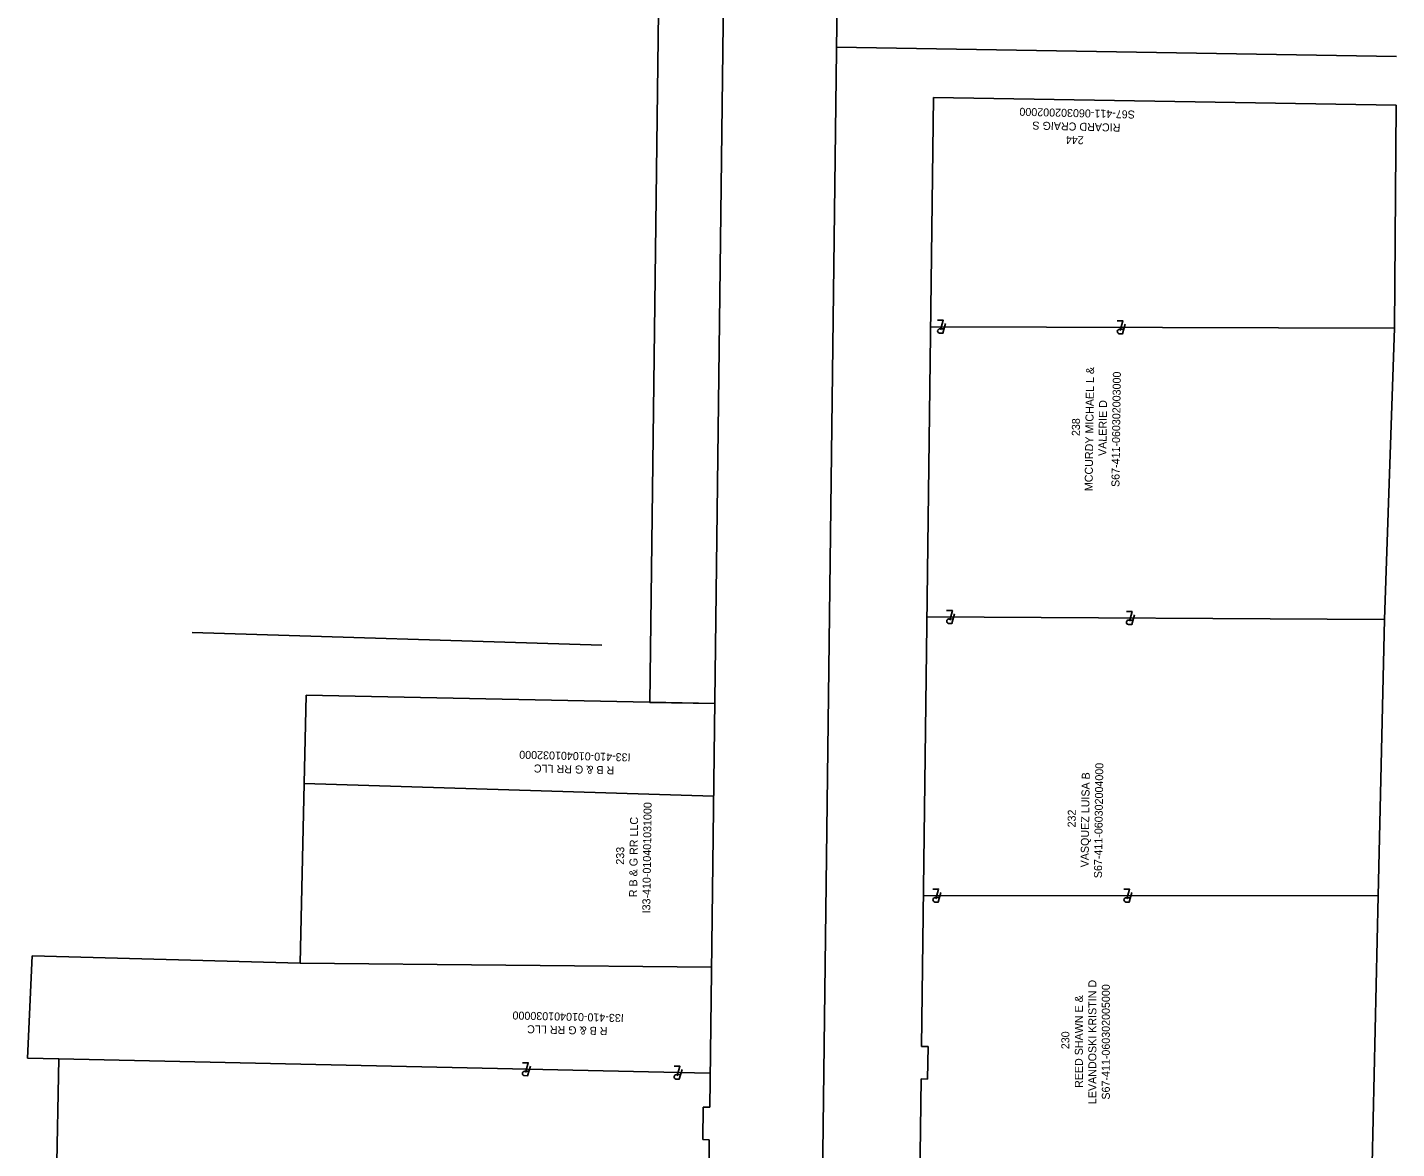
# Model space of a CAD drawing. Extents: x 1652206 to 1653153, y 604222 to 614600.
# Drawn here: x 1652315.3 to 1652737, y 607628 to 607973.5 of the extents above; entities that cross this region are included whole.
import ezdxf

# ---------------------------------------------------------------- set-up
doc = ezdxf.new("R2010")
doc.units = 0
for name, color, linetype in [('_CIVIL_CONSTRUCTION', 7, 'Continuous'), ('DT_X_Contour_Minor', 7, 'Continuous'), ('GE_P_Alignment_100_Bearings', 7, 'Continuous'), ('GE_P_Alignment_100_Cardinal_Points', 7, 'Continuous'), ('GE_P_Alignment_100_Curve_Data', 7, 'Continuous'), ('GE_P_Alignment_100_Distances', 7, 'Continuous')]:
    doc.layers.add(name, color=color, linetype=linetype)

msp = doc.modelspace()

# ---------------------------------------------------------------- linework, layer by layer
at = {"layer": '_CIVIL_CONSTRUCTION'}
for p, q in [((1652550.86, 606872.07), (1652575.14, 608815.48)), ((1652736.99, 607964.54), (1652564.54, 607967.42))]:
    msp.add_line(p, q, dxfattribs=at)
at = {"layer": 'DT_X_Contour_Minor'}
msp.add_lwpolyline([(1652527.01, 607765.18), (1652507.01, 607765.43), (1652518.27, 608666.13)], dxfattribs=at)
at = {"layer": 'GE_P_Alignment_100_Bearings'}
for p, q in [((1652736.85, 607949.54), (1652736.33, 607880.82)), ((1652736.33, 607880.82), (1652593.47, 607881.24)), ((1652596.82, 607881.23), (1652596.82, 607881.23)), ((1652652.15, 607881.07), (1652652.15, 607881.07)), ((1652736.33, 607880.82), (1652733.23, 607790.98)), ((1652597.62, 607880.6), (1652596.33, 607880.6)), ((1652652.95, 607880.44), (1652651.65, 607880.44)), ((1652733.23, 607790.98), (1652592.35, 607791.83)), ((1652600.43, 607791.16), (1652599.14, 607791.17)), ((1652599.63, 607791.79), (1652599.63, 607791.79)), ((1652655.8, 607790.83), (1652654.5, 607790.84)), ((1652655, 607791.46), (1652655, 607791.46)), ((1652733.23, 607790.98), (1652731.35, 607705.9)), ((1652492.21, 607783.15), (1652366.11, 607787.05)), ((1652400.56, 607740.52), (1652401.16, 607767.72)), ((1652401.16, 607767.72), (1652527.01, 607765.08)), ((1652399.3, 607685.1), (1652400.56, 607740.52)), ((1652400.56, 607740.52), (1652526.66, 607736.62)), ((1652731.35, 607705.9), (1652591.28, 607705.92)), ((1652596.18, 607705.3), (1652594.89, 607705.3)), ((1652595.38, 607705.92), (1652595.38, 607705.92)), ((1652655.02, 607705.29), (1652653.72, 607705.29)), ((1652654.21, 607705.92), (1652654.21, 607705.92)), ((1652731.35, 607705.9), (1652729.47, 607623.32)), ((1652315.32, 607655.82), (1652316.82, 607687.38)), ((1652316.82, 607687.38), (1652399.3, 607685.1)), ((1652526, 607683.88), (1652399.3, 607685.1)), ((1652399.3, 607685.1), (1652526, 607683.88)), ((1652325, 607655.62), (1652315.32, 607655.82)), ((1652322.74, 607543.82), (1652325, 607655.62)), ((1652325, 607655.62), (1652515.94, 607651.38)), ((1652515.94, 607651.38), (1652325, 607655.62)), ((1652469.77, 607651.79), (1652468.47, 607651.82)), ((1652468.98, 607652.43), (1652468.98, 607652.43)), ((1652516.47, 607650.75), (1652515.18, 607650.78)), ((1652515.69, 607651.39), (1652515.69, 607651.39)), ((1652515.94, 607651.38), (1652525.59, 607651.17)), ((1652525.59, 607651.17), (1652515.94, 607651.38))]:
    msp.add_line(p, q, dxfattribs=at)
for points in [[(1652596.55, 607880.27), (1652597.35, 607883.22), (1652595.61, 607883.23)], [(1652598.05, 607882.19), (1652597.26, 607879.23), (1652596.22, 607879.23)], [(1652651.88, 607880.11), (1652652.68, 607883.06), (1652650.93, 607883.07)], [(1652653.37, 607882.03), (1652652.58, 607879.07), (1652651.55, 607879.07)], [(1652599.36, 607790.83), (1652600.17, 607793.78), (1652598.42, 607793.79)], [(1652600.86, 607792.75), (1652600.06, 607789.79), (1652599.03, 607789.8)], [(1652654.72, 607790.5), (1652655.53, 607793.45), (1652653.79, 607793.46)], [(1652656.22, 607792.42), (1652655.43, 607789.46), (1652654.39, 607789.46)], [(1652595.12, 607704.96), (1652595.91, 607707.92), (1652594.16, 607707.92)], [(1652653.95, 607704.96), (1652654.74, 607707.91), (1652652.99, 607707.91)], [(1652596.6, 607706.89), (1652595.82, 607703.93), (1652594.79, 607703.93)], [(1652655.44, 607706.88), (1652654.65, 607703.92), (1652653.62, 607703.92)], [(1652468.69, 607651.47), (1652469.55, 607654.41), (1652467.8, 607654.45)], [(1652470.22, 607653.37), (1652469.37, 607650.42), (1652468.34, 607650.45)], [(1652515.4, 607650.44), (1652516.26, 607653.37), (1652514.51, 607653.41)], [(1652516.93, 607652.33), (1652516.08, 607649.38), (1652515.05, 607649.41)]]:
    msp.add_lwpolyline(points, dxfattribs=at)
for centre, start, end in [((1652596.33, 607879.91), 90.3058, 261.1629), ((1652651.66, 607879.76), 90.3058, 261.1629), ((1652599.14, 607790.48), 90.1261, 260.9832), ((1652654.5, 607790.15), 90.1261, 260.9832), ((1652594.89, 607704.61), 90.4629, 261.32), ((1652653.72, 607704.6), 90.4629, 261.32), ((1652468.46, 607651.13), 89.1989, 260.0561), ((1652515.17, 607650.09), 89.1989, 260.0561)]:
    msp.add_arc(centre, 0.69, start, end, dxfattribs=at)
at = {"layer": 'GE_P_Alignment_100_Curve_Data'}
for p, q in [((1652592.7, 607659.4), (1652590.7, 607659.42)), ((1652592.57, 607649.4), (1652592.7, 607659.4)), ((1652590.57, 607649.43), (1652592.57, 607649.4))]:
    msp.add_line(p, q, dxfattribs=at)
at = {"layer": 'GE_P_Alignment_100_Distances'}
for p, q in [((1652525.46, 607640.72), (1652538.25, 608664.92)), ((1652590.7, 607659.42), (1652594.35, 607951.92)), ((1652736.85, 607949.54), (1652594.35, 607951.92)), ((1652586.25, 607303.66), (1652590.57, 607649.43)), ((1652523.33, 607630.75), (1652523.46, 607640.75)), ((1652523.46, 607640.75), (1652525.46, 607640.72)), ((1652521.14, 607294.92), (1652525.33, 607630.72)), ((1652525.33, 607630.72), (1652523.33, 607630.75))]:
    msp.add_line(p, q, dxfattribs=at)

# ---------------------------------------------------------------- texts
at = {"layer": 'GE_P_Alignment_100_Cardinal_Points'}
for s, height, rotation, p in [('S67-411-060302002000', 2.4653, 178.565, (1652656.41, 607947.83)), ('RICARD CRAIG S', 2.4653, 178.565, (1652651.96, 607943.79)), ('244', 2.465, 178.565, (1652640.66, 607939.92)), ('MCCURDY MICHAEL L & ', 2.4653, 89.2843, (1652643.36, 607830.54)), ('S67-411-060302003000', 2.4653, 89.2843, (1652651.63, 607831.83)), ('VALERIE D', 2.465, 89.2843, (1652647.6, 607841.39)), ('238', 2.465, 89.2843, (1652639.42, 607847.52)), ('I33-410-010401032000', 2.4653, 178.565, (1652501.1, 607749.73)), ('R B & G RR LLC', 2.4653, 178.565, (1652496.06, 607745.74)), ('S67-411-060302004000', 2.4653, 89.2843, (1652646.24, 607711.28)), ('VASQUEZ LUISA B', 2.4653, 89.2843, (1652642.13, 607714.62)), ('I33-410-010401031000', 2.4653, 89.2843, (1652507.14, 607700.43)), ('R B & G RR LLC', 2.4653, 89.2843, (1652503.08, 607705.43)), ('232', 2.465, 89.2843, (1652638.13, 607726.93)), ('233', 2.465, 89.2843, (1652499.06, 607715.45)), ('LEVANDOSKI KRISTIN D', 2.4653, 90, (1652644.52, 607641.68)), ('S67-411-060302005000', 2.4653, 90, (1652648.67, 607643.06)), ('REED SHAWN E & ', 2.4653, 90, (1652640.36, 607646.65)), ('I33-410-010401030000', 2.4653, 178.565, (1652499.02, 607669.39)), ('R B & G RR LLC', 2.4653, 178.565, (1652493.98, 607665.39)), ('230', 2.465, 90, (1652636.21, 607658.6))]:
    msp.add_text(s, height=height, rotation=rotation, dxfattribs=at).set_placement(p)

doc.saveas('drawing.dxf')
